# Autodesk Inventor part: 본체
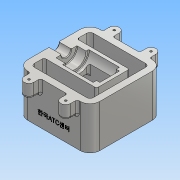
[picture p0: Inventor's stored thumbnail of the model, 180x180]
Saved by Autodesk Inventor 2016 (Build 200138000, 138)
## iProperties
Created: 2018-01
Part Number: 본체
Material: 알루미늄 6061
Document SubType Name: Modeling
Designer: Administrator
Density: 2.7 g/cm^3
Appearance: 알루미늄 - 평지
Mass: 995.308 g
Surface Area: 834.574 cm^2
Volume: 368.633 cm^3
Author: Administrator
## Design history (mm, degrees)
sketch "스케치1"
  geometry: L1 (-55, -55)-(55, -55); L2 (55, -55)-(55, 55); L3 (55, 55)-(-55, 55); L4 (-55, 55)-(-55, -55); L5 (-55, -55)-(55, 55); L6 (55, -55)-(-55, 55); 1 further point
  constraints: 12 end point, 2 midpoint, 2 parallel, 1 horizontal, 1 perpendicular
  dimensions: "d0" = 110 distance of L3.end L2.end; "d1" = 110 distance of L2.end L1.end
extrude "돌출1" new body sketch "스케치1" distance "d2" = 65; taper "d3" = 0 deg
sketch "스케치3"
  geometry: L1 (-55, 55)-(-55, -55) reference; L2 (-55, 0)-(30, 0); L3 (-55, 7.5)-(-36, 7.5); L4 (-36, 7.5)-(-36, 16); L5 (-36, 16)-(-22, 16); L6 (-22, 16)-(-22, 20); L7 (-22, 20)-(25, 20); L8 (30, 15)-(30, 0); L9 (25, 20)-(25, 15); L10 (25, 15)-(30, 15); 1 further point
  constraints: 18 end point, 6 perpendicular, 1 horizontal, 1 midpoint, 1 parallel, 1 point on line, 1 vertical
  dimensions: "d13" = 15 diameter of L3 L2; "d14" = 32 diameter of L5 L2; "d16" = 30 diameter of L10 L2; "d17" = 19 distance between parallel lines of L1 L4; "d18" = 5 distance of L9.end L8.start; "d19" = 47 distance of L6.end L7.end; "d20" = 14 distance of L4.end L5.end; "d23" = 40 diameter of L7 L2
revolve "회전1" sketch "스케치3" stored, may be unused: angle "d24" = 90 deg
sketch "스케치4"
  geometry: L1 (55, 0)-(55, 65) reference; L2 (55, 29.061)-(17, 39.243); L3 (55, 11.061)-(-20, 31.157); L4 (-55, 65)-(55, 65) reference; L5 (-35, 65)-(-35, 30); L6 (-35, 30)-(45, 8.564); L7 (45, 8.564)-(45, 0); L8 (-55, 0)-(55, 0) reference; L9 (-45, 65)-(-45, 0); L10 (-55, 0)-(-55, 65) reference; L11 (17, 39.243)-(17, 65); L12 (-25, 65)-(22, 65) reference; L13 (-20, 31.157)-(-20, 65); 4 further points
  constraints: 16 end point, 8 point on line, 3 parallel, 1 perpendicular, 1 vertical
  dimensions: "d26" = 18 distance of L3.start L2.start; "d27" = 75 deg angle of L1 L2; "d29" = 10 distance between parallel lines of L10 L9; "d30" = 20 distance between parallel lines of L10 L5; "d32" = 105 deg angle of L7 L6; "d33" = 30 vertical distance of L8.start L5.end; "d34" = 5 distance between parallel lines of L6 L3; "d35" = 10 distance between parallel lines of L1 L7; "d42" = 37 distance between parallel lines of L13 L11
extrude "돌출2" cut sketch "스케치4" stored distance "d36" = 30; taper "d37" = 0 deg
sketch "스케치6"
  geometry: L1 (55, 55)-(-55, 55) reference; L2 (-55, 55)-(-55, 7.5) reference; L3 (-35.5, 55)-(-20.5, 55); L4 (-20.5, 55)-(-20.5, 65); L5 (-20.5, 65)-(-35.5, 65); L6 (-35.5, 65)-(-35.5, 55); A1 r 7.5 centre (-28, 65) between (-20.5, 65) and (-35.5, 65); 1 further point
  constraints: 8 end point, 2 parallel, 2 point on circle, 1 centre point, 1 horizontal, 1 midpoint, 1 perpendicular, 1 point on line
  dimensions: "d43" = 27 distance from line of A1.centre L2; "d44" = 10 distance between parallel lines of L1 L5; "d45" = 7.5 radius of A1
extrude "돌출3" join sketch "스케치6" distance "d46" = 20; taper "d47" = 0 deg
hole "구멍1" diameter "d50" = 3.242; stored, may be unused: countersink angle "d54" = 90 deg, drill point angle "d56" = 118 deg; dims "d51" = 9, "d52" = 4, "d53" = 2, "d55" = 11, "d100" = 10, "d101" = 10
sketch "스케치8"
  geometry: L1 (-20.5, -55)-(20.5, -55) reference; L2 (55, -55)-(55, 55) reference; L3 (20.5, 55)-(-20.5, 55) reference; L4 (-55, 55)-(-55, 7.5) reference; L5 (-45, 45)-(-45, 25); L6 (-45, 25)-(35, 25); L7 (35, 25)-(35, -25); L8 (35, -25)-(-45, -25); L9 (-45, -25)-(-45, -45); L10 (-45, -45)-(45, -45); L11 (45, -45)-(45, 45); L12 (45, 45)-(-45, 45); 2 further points
  constraints: 16 end point, 6 perpendicular, 2 point on line, 1 horizontal alignment, 1 midpoint, 1 vertical
  dimensions: "d60" = 10 distance between parallel lines of L5 L4; "d61" = 10 distance between parallel lines of L12 L3; "d62" = 10 distance between parallel lines of L2 L11; "d63" = 10 distance between parallel lines of L1 L10; "d64" = 20 distance between parallel lines of L2 L7; "d65" = 50 distance between parallel lines of L8 L6
extrude "돌출4" cut sketch "스케치8" stored distance "d66" = 0; taper "d67" = 0 deg
sketch "스케치9"
  geometry: L1 (-55, 0)-(55, 0) reference; L2 (45, 0)-(45, 8.564); L3 (45, 8.564)-(-35, 30); L4 (-35, 65)-(-35, 0) reference; L5 (-20, 31.157)-(55, 11.061) reference; L6 (55, 0)-(55, 65) reference; 1 further point
  constraints: 4 end point, 2 point on line, 1 perpendicular
  dimensions: "d69" = 105 deg angle of L2 L3; "d70" = 30 distance from line of L1 L3.end; "d72" = 10 distance between parallel lines of L6 L2
extrude "돌출5" cut sketch "스케치9" stored distance "d73" = 90; taper "d74" = 0 deg
fillet "모깎기7" dims "d82" = 15
chamfer "모따기1" distance "d83" = 1; stored, may be unused: second distance "d84" = 2, angle "d85" = 45 deg
fillet "모깎기8" dims "d86" = 3
fillet "모깎기9" dims "d87" = 3
fillet "모깎기10" dims "d88" = 3
fillet "모깎기11" dims "d89" = 3
fillet "모깎기13" dims "d91" = 3
sketch "스케치10"
  geometry: L1 (0, 0)-(80, 0) reference; L2 (-15, 65)-(-15, 0) reference; 2 further points
  constraints: 1 other
  dimensions: "d92" = 20 distance from line of L1 point (40, 20); "d93" = 55 distance from line of L2 point (40, 20)
feature "엠보싱1" sketch "스케치10" dims "d0" = 110, "d1" = 110, "d94" = 0.5, "d95" = 0
fillet "모깎기14" dims "d96" = 5
fillet "모깎기15" dims "d97" = 3
fillet "모깎기16" dims "d98" = 1
node "솔리드1"
pattern_linear "직사각형 패턴1" dims "d59" = 56
mirror "대칭2"
